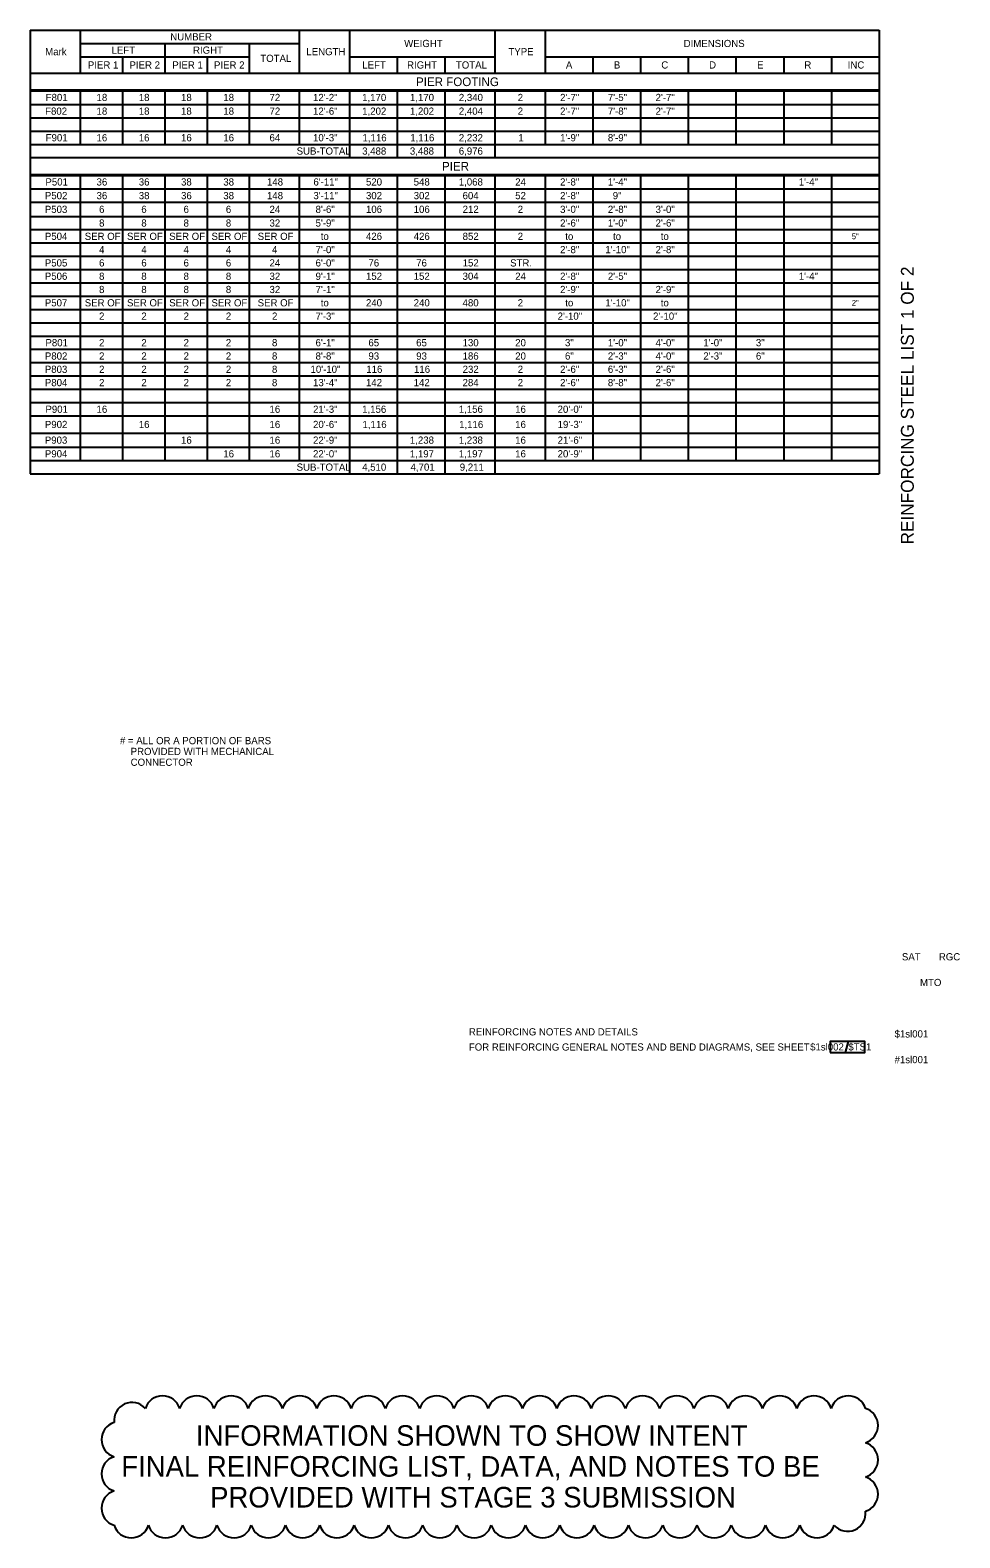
# Model space of a CAD drawing. Extents: x -16.6 to 33.3, y -8.6 to 39.2.
# Drawn here: x 15.24 to 33.32, y -8.63 to 20.7 of the extents above; entities that cross this region are included whole.
import ezdxf

# ---------------------------------------------------------------- set-up
doc = ezdxf.new("R2010")
doc.units = 0
for name, color, linetype in [('BR_X_Beam_Centerline', 7, 'Continuous'), ('BR_X_Beam_Object', 7, 'Continuous'), ('Default', 7, 'Continuous')]:
    doc.layers.add(name, color=color, linetype=linetype)

msp = doc.modelspace()

# ---------------------------------------------------------------- linework, layer by layer
at = {"layer": 'BR_X_Beam_Centerline'}
msp.add_line((31.098, 0.814), (31.153, 1.029), dxfattribs=at)
msp.add_lwpolyline([(30.796, 0.814), (31.47, 0.814), (31.47, 1.029), (30.796, 1.029)], close=True, dxfattribs=at)
for centre, radius, start, end in [((17.221, -6.342), 0.349, 41.6402, 186.6402), ((17.816, -6.215), 0.35, 17.5, 162.5), ((18.482, -6.215), 0.35, 17.5, 162.5), ((19.149, -6.215), 0.35, 17.5, 162.5), ((19.816, -6.215), 0.35, 17.5, 162.5), ((20.483, -6.215), 0.35, 17.5, 162.5), ((21.149, -6.215), 0.35, 17.5, 162.5), ((21.816, -6.215), 0.35, 17.5, 162.5), ((22.483, -6.215), 0.35, 17.5, 162.5), ((23.15, -6.215), 0.35, 17.5, 162.5), ((23.816, -6.215), 0.35, 17.5, 162.5), ((24.483, -6.215), 0.35, 17.5, 162.5), ((25.15, -6.215), 0.35, 17.5, 162.5), ((25.817, -6.215), 0.35, 17.5, 162.5), ((26.483, -6.215), 0.35, 17.5, 162.5), ((27.15, -6.215), 0.35, 17.5, 162.5), ((27.817, -6.215), 0.35, 17.5, 162.5), ((28.484, -6.215), 0.35, 17.5, 162.5), ((29.15, -6.215), 0.35, 17.5, 162.5), ((29.817, -6.215), 0.35, 17.5, 162.5), ((30.484, -6.215), 0.35, 17.5, 162.5), ((31.151, -6.215), 0.35, 17.5, 162.5), ((31.379, -6.443), 0.35, 287.5, 72.5), ((16.979, -6.716), 0.35, 107.5, 252.5), ((31.379, -7.11), 0.35, 287.5, 72.5), ((16.979, -7.382), 0.35, 107.5, 252.5), ((31.379, -7.777), 0.35, 287.5, 72.5), ((16.979, -8.049), 0.35, 107.5, 252.5), ((31.137, -8.151), 0.349, 221.6402, 6.6402), ((17.208, -8.277), 0.35, 197.5, 342.5), ((17.874, -8.277), 0.35, 197.5, 342.5), ((18.541, -8.277), 0.35, 197.5, 342.5), ((19.208, -8.277), 0.35, 197.5, 342.5), ((19.875, -8.277), 0.35, 197.5, 342.5), ((20.541, -8.277), 0.35, 197.5, 342.5), ((21.208, -8.277), 0.35, 197.5, 342.5), ((21.875, -8.277), 0.35, 197.5, 342.5), ((22.542, -8.277), 0.35, 197.5, 342.5), ((23.208, -8.277), 0.35, 197.5, 342.5), ((23.875, -8.277), 0.35, 197.5, 342.5), ((24.542, -8.277), 0.35, 197.5, 342.5), ((25.209, -8.277), 0.35, 197.5, 342.5), ((25.875, -8.277), 0.35, 197.5, 342.5), ((26.542, -8.277), 0.35, 197.5, 342.5), ((27.209, -8.277), 0.35, 197.5, 342.5), ((27.876, -8.277), 0.35, 197.5, 342.5), ((28.542, -8.277), 0.35, 197.5, 342.5), ((29.209, -8.277), 0.35, 197.5, 342.5), ((29.876, -8.277), 0.35, 197.5, 342.5), ((30.543, -8.277), 0.35, 197.5, 342.5)]:
    msp.add_arc(centre, radius, start, end, dxfattribs=at)
at = {"layer": 'Default'}
for p, q in [((15.242, 20.698), (31.752, 20.698)), ((15.242, 20.698), (15.242, 19.516)), ((16.216, 20.698), (16.216, 19.861)), ((20.476, 20.698), (20.476, 19.861)), ((21.45, 20.698), (21.45, 19.861)), ((24.281, 20.698), (24.281, 19.861)), ((25.254, 20.698), (25.254, 19.861)), ((31.752, 20.698), (31.752, 19.516)), ((16.216, 20.439), (20.476, 20.439)), ((17.859, 20.439), (17.859, 19.861)), ((19.503, 20.439), (19.503, 19.861)), ((16.216, 20.181), (19.503, 20.181)), ((17.037, 20.181), (17.037, 19.861)), ((18.681, 20.181), (18.681, 19.861)), ((21.45, 20.181), (24.281, 20.181)), ((22.378, 20.181), (22.378, 19.861)), ((23.307, 20.181), (23.307, 19.861)), ((25.254, 20.181), (31.752, 20.181)), ((26.183, 20.181), (26.183, 19.861)), ((27.111, 20.181), (27.111, 19.861)), ((28.039, 20.181), (28.039, 19.861)), ((28.967, 20.181), (28.967, 19.861)), ((29.896, 20.181), (29.896, 19.861)), ((30.824, 20.181), (30.824, 19.861)), ((15.242, 19.861), (31.752, 19.861)), ((15.242, 19.536), (31.752, 19.536)), ((15.242, 19.536), (15.242, 17.873)), ((15.242, 19.516), (31.752, 19.516)), ((16.216, 19.516), (16.216, 18.476)), ((17.037, 19.516), (17.037, 18.476)), ((17.859, 19.516), (17.859, 18.476)), ((18.681, 19.516), (18.681, 18.476)), ((19.503, 19.536), (19.503, 18.476)), ((20.476, 19.516), (20.476, 18.476)), ((21.45, 19.516), (21.45, 18.218)), ((22.378, 19.516), (22.378, 18.218)), ((23.307, 19.536), (23.307, 18.218)), ((24.281, 19.516), (24.281, 18.218)), ((25.254, 19.516), (25.254, 18.476)), ((26.183, 19.516), (26.183, 18.476)), ((27.111, 19.516), (27.111, 18.476)), ((28.039, 19.516), (28.039, 18.476)), ((28.967, 19.516), (28.967, 18.476)), ((29.896, 19.516), (29.896, 18.476)), ((30.824, 19.516), (30.824, 18.476)), ((31.752, 19.536), (31.752, 17.873)), ((15.242, 19.252), (31.752, 19.252)), ((15.242, 18.994), (31.752, 18.994)), ((15.242, 18.735), (31.752, 18.735)), ((15.242, 18.476), (31.752, 18.476)), ((15.242, 18.218), (31.752, 18.218)), ((15.242, 17.893), (31.752, 17.893)), ((15.242, 17.893), (15.242, 12.07)), ((19.503, 17.893), (19.503, 12.329)), ((23.307, 17.893), (23.307, 12.07)), ((31.752, 17.893), (31.752, 12.07)), ((15.242, 17.873), (31.752, 17.873)), ((15.242, 17.609), (31.752, 17.609)), ((16.216, 17.873), (16.216, 12.329)), ((17.037, 17.873), (17.037, 12.329)), ((17.859, 17.873), (17.859, 12.329)), ((18.681, 17.873), (18.681, 12.329)), ((20.476, 17.873), (20.476, 12.329)), ((21.45, 17.873), (21.45, 12.07)), ((22.378, 17.873), (22.378, 12.07)), ((24.281, 17.873), (24.281, 12.07)), ((25.254, 17.873), (25.254, 12.329)), ((26.183, 17.873), (26.183, 12.329)), ((27.111, 17.873), (27.111, 12.329)), ((28.039, 17.873), (28.039, 12.329)), ((28.967, 17.873), (28.967, 12.329)), ((29.896, 17.873), (29.896, 12.329)), ((30.824, 17.873), (30.824, 12.329)), ((15.242, 17.35), (31.752, 17.35)), ((15.242, 17.076), (31.752, 17.076)), ((15.242, 16.818), (31.752, 16.818)), ((15.242, 16.559), (31.752, 16.559)), ((15.242, 16.3), (31.752, 16.3)), ((15.242, 16.042), (31.752, 16.042)), ((15.242, 15.783), (31.752, 15.783)), ((15.242, 15.524), (31.752, 15.524)), ((15.242, 15.266), (31.752, 15.266)), ((15.242, 15.007), (31.752, 15.007)), ((15.242, 14.748), (31.752, 14.748)), ((15.242, 14.49), (31.752, 14.49)), ((15.242, 14.231), (31.752, 14.231)), ((15.242, 13.972), (31.752, 13.972)), ((15.242, 13.713), (31.752, 13.713)), ((15.242, 13.455), (31.752, 13.455)), ((15.242, 13.196), (31.752, 13.196)), ((15.242, 12.861), (31.752, 12.861)), ((15.242, 12.587), (31.752, 12.587)), ((15.242, 12.329), (31.752, 12.329)), ((15.242, 12.07), (31.753, 12.07))]:
    msp.add_line(p, q, dxfattribs=at)

# ---------------------------------------------------------------- texts
at = {"layer": 'BR_X_Beam_Centerline'}
for s, height, p in [('NUMBER', 0.14, (17.966, 20.499)), ('Mark', 0.14, (15.534, 20.21)), ('LEFT', 0.14, (16.824, 20.24)), ('RIGHT', 0.14, (18.409, 20.24)), ('LENGTH', 0.14, (20.613, 20.21)), ('WEIGHT', 0.14, (22.515, 20.369)), ('TYPE', 0.14, (24.542, 20.21)), ('DIMENSIONS', 0.14, (27.95, 20.369)), ('PIER 1', 0.14, (16.364, 19.951)), ('PIER 2', 0.14, (17.174, 19.951)), ('PIER 1', 0.14, (18.007, 19.951)), ('PIER 2', 0.14, (18.817, 19.951)), ('TOTAL', 0.14, (19.717, 20.08)), ('LEFT', 0.14, (21.701, 19.951)), ('RIGHT', 0.14, (22.571, 19.951)), ('TOTAL', 0.14, (23.521, 19.951)), ('A', 0.14, (25.66, 19.951)), ('B', 0.14, (26.593, 19.951)), ('C', 0.14, (27.515, 19.951)), ('D', 0.14, (28.444, 19.951)), ('E', 0.14, (29.377, 19.951)), ('R', 0.14, (30.297, 19.951)), ('INC', 0.14, (31.14, 19.951)), ('PIER FOOTING', 0.16799, (22.746, 19.61)), ('F801', 0.14, (15.544, 19.319)), ('18', 0.14, (16.533, 19.319)), ('18', 0.14, (17.354, 19.319)), ('18', 0.14, (18.176, 19.319)), ('18', 0.14, (18.998, 19.319)), ('72', 0.14, (19.896, 19.319)), ('12\'-2"', 0.14, (20.743, 19.319)), ('1,170', 0.14, (21.698, 19.319)), ('1,170', 0.14, (22.627, 19.319)), ('2,340', 0.14, (23.578, 19.319)), ('2', 0.14, (24.723, 19.319)), ('2\'-7"', 0.14, (25.547, 19.319)), ('7\'-5"', 0.14, (26.476, 19.319)), ('2\'-7"', 0.14, (27.404, 19.319)), ('F802', 0.14, (15.533, 19.053)), ('18', 0.14, (16.533, 19.053)), ('18', 0.14, (17.354, 19.053)), ('18', 0.14, (18.176, 19.053)), ('18', 0.14, (18.998, 19.053)), ('72', 0.14, (19.896, 19.053)), ('12\'-6"', 0.14, (20.743, 19.053)), ('1,202', 0.14, (21.699, 19.053)), ('1,202', 0.14, (22.627, 19.053)), ('2,404', 0.14, (23.578, 19.053)), ('2', 0.14, (24.723, 19.053)), ('2\'-7"', 0.14, (25.547, 19.053)), ('7\'-8"', 0.14, (26.476, 19.053)), ('2\'-7"', 0.14, (27.404, 19.053)), ('F901', 0.14, (15.544, 18.536)), ('16', 0.14, (16.533, 18.536)), ('16', 0.14, (17.354, 18.536)), ('16', 0.14, (18.176, 18.536)), ('16', 0.14, (18.998, 18.536)), ('64', 0.14, (19.896, 18.536)), ('10\'-3"', 0.14, (20.743, 18.536)), ('1,116', 0.14, (21.705, 18.536)), ('1,116', 0.14, (22.633, 18.536)), ('2,232', 0.14, (23.578, 18.536)), ('1', 0.14, (24.735, 18.536)), ('1\'-9"', 0.14, (25.547, 18.536)), ('8\'-9"', 0.14, (26.476, 18.536)), ('SUB-TOTAL', 0.14, (20.424, 18.277)), ('3,488', 0.14, (21.698, 18.277)), ('3,488', 0.14, (22.626, 18.277)), ('6,976', 0.14, (23.577, 18.277)), ('PIER', 0.168, (23.251, 17.966)), ('P501', 0.14, (15.539, 17.676)), ('36', 0.14, (16.533, 17.676)), ('36', 0.14, (17.354, 17.676)), ('38', 0.14, (18.176, 17.676)), ('38', 0.14, (18.998, 17.676)), ('148', 0.14, (19.847, 17.676)), ('6\'-11"', 0.14, (20.75, 17.676)), ('520', 0.14, (21.772, 17.676)), ('548', 0.14, (22.7, 17.676)), ('1,068', 0.14, (23.577, 17.676)), ('24', 0.14, (24.674, 17.676)), ('2\'-8"', 0.14, (25.547, 17.676)), ('1\'-4"', 0.14, (26.476, 17.676)), ('1\'-4"', 0.14, (30.189, 17.676)), ('P502', 0.14, (15.528, 17.41)), ('36', 0.14, (16.533, 17.41)), ('38', 0.14, (17.354, 17.41)), ('36', 0.14, (18.176, 17.41)), ('38', 0.14, (18.998, 17.41)), ('148', 0.14, (19.847, 17.41)), ('3\'-11"', 0.14, (20.75, 17.41)), ('302', 0.14, (21.772, 17.41)), ('302', 0.14, (22.7, 17.41)), ('604', 0.14, (23.651, 17.41)), ('52', 0.14, (24.674, 17.41)), ('2\'-8"', 0.14, (25.547, 17.41)), ('9"', 0.14, (26.571, 17.41)), ('P503', 0.14, (15.527, 17.143)), ('8', 0.14, (16.582, 16.877)), ('6', 0.14, (16.582, 17.143)), ('8', 0.14, (17.403, 16.877)), ('6', 0.14, (17.403, 17.143)), ('8', 0.14, (18.225, 16.877)), ('6', 0.14, (18.225, 17.143)), ('8', 0.14, (19.047, 16.877)), ('6', 0.14, (19.047, 17.143)), ('32', 0.14, (19.896, 16.877)), ('24', 0.14, (19.896, 17.143)), ('8\'-6"', 0.14, (20.792, 17.143)), ('5\'-9"', 0.14, (20.792, 16.877)), ('106', 0.14, (21.772, 17.143)), ('106', 0.14, (22.7, 17.143)), ('212', 0.14, (23.652, 17.143)), ('2', 0.14, (24.723, 17.143)), ('3\'-0"', 0.14, (25.547, 17.143)), ('2\'-6"', 0.14, (25.547, 16.877)), ('2\'-8"', 0.14, (26.476, 17.143)), ('1\'-0"', 0.14, (26.476, 16.877)), ('3\'-0"', 0.14, (27.404, 17.143)), ('2\'-6"', 0.14, (27.404, 16.877)), ('P504', 0.14, (15.528, 16.618)), ('SER OF', 0.14, (16.303, 16.618)), ('SER OF', 0.14, (17.125, 16.618)), ('SER OF', 0.14, (17.946, 16.618)), ('SER OF', 0.14, (18.768, 16.618)), ('SER OF', 0.14, (19.666, 16.618)), ('to', 0.14, (20.893, 16.618)), ('426', 0.14, (21.772, 16.618)), ('426', 0.14, (22.7, 16.618)), ('852', 0.14, (23.652, 16.618)), ('2', 0.14, (24.723, 16.618)), ('to', 0.14, (25.648, 16.618)), ('to', 0.14, (26.577, 16.618)), ('to', 0.14, (27.505, 16.618)), ('5"', 0.112, (31.219, 16.632)), ('4', 0.14, (16.582, 16.36)), ('4', 0.14, (17.404, 16.36)), ('4', 0.14, (18.225, 16.36)), ('4', 0.14, (19.047, 16.36)), ('4', 0.14, (19.945, 16.36)), ('7\'-0"', 0.14, (20.792, 16.36)), ('2\'-8"', 0.14, (25.547, 16.36)), ('1\'-10"', 0.14, (26.427, 16.36)), ('2\'-8"', 0.14, (27.404, 16.36)), ('P505', 0.14, (15.527, 16.101)), ('6', 0.14, (16.582, 16.101)), ('6', 0.14, (17.403, 16.101)), ('6', 0.14, (18.225, 16.101)), ('6', 0.14, (19.047, 16.101)), ('24', 0.14, (19.896, 16.101)), ('6\'-0"', 0.14, (20.792, 16.101)), ('76', 0.14, (21.82, 16.101)), ('76', 0.14, (22.749, 16.101)), ('152', 0.14, (23.652, 16.101)), ('STR.', 0.14, (24.575, 16.101)), ('P506', 0.14, (15.527, 15.842)), ('8', 0.14, (16.582, 15.842)), ('8', 0.14, (17.403, 15.842)), ('8', 0.14, (18.225, 15.842)), ('8', 0.14, (19.047, 15.842)), ('32', 0.14, (19.896, 15.842)), ('9\'-1"', 0.14, (20.792, 15.842)), ('152', 0.14, (21.772, 15.842)), ('152', 0.14, (22.7, 15.842)), ('304', 0.14, (23.651, 15.842)), ('24', 0.14, (24.674, 15.842)), ('2\'-8"', 0.14, (25.547, 15.842)), ('2\'-5"', 0.14, (26.476, 15.842)), ('1\'-4"', 0.14, (30.189, 15.842)), ('8', 0.14, (16.582, 15.584)), ('8', 0.14, (17.403, 15.584)), ('8', 0.14, (18.225, 15.584)), ('8', 0.14, (19.047, 15.584)), ('32', 0.14, (19.896, 15.584)), ('7\'-1"', 0.14, (20.792, 15.584)), ('2\'-9"', 0.14, (25.547, 15.584)), ('2\'-9"', 0.14, (27.404, 15.584)), ('P507', 0.14, (15.527, 15.325)), ('SER OF', 0.14, (16.303, 15.325)), ('SER OF', 0.14, (17.125, 15.325)), ('SER OF', 0.14, (17.946, 15.325)), ('SER OF', 0.14, (18.768, 15.325)), ('SER OF', 0.14, (19.666, 15.325)), ('to', 0.14, (20.893, 15.325)), ('240', 0.14, (21.772, 15.325)), ('240', 0.14, (22.7, 15.325)), ('480', 0.14, (23.651, 15.325)), ('2', 0.14, (24.723, 15.325)), ('to', 0.14, (25.648, 15.325)), ('1\'-10"', 0.14, (26.427, 15.325)), ('to', 0.14, (27.505, 15.325)), ('2"', 0.112, (31.219, 15.339)), ('2', 0.14, (16.582, 15.066)), ('2', 0.14, (17.404, 15.066)), ('2', 0.14, (18.226, 15.066)), ('2', 0.14, (19.047, 15.066)), ('2', 0.14, (19.945, 15.066)), ('7\'-3"', 0.14, (20.792, 15.066)), ('2\'-10"', 0.14, (25.499, 15.066)), ('2\'-10"', 0.14, (27.355, 15.066)), ('P801', 0.14, (15.539, 14.549)), ('2', 0.14, (16.582, 14.549)), ('2', 0.14, (17.404, 14.549)), ('2', 0.14, (18.226, 14.549)), ('2', 0.14, (19.047, 14.549)), ('8', 0.14, (19.944, 14.549)), ('6\'-1"', 0.14, (20.792, 14.549)), ('65', 0.14, (21.82, 14.549)), ('65', 0.14, (22.748, 14.549)), ('130', 0.14, (23.651, 14.549)), ('20', 0.14, (24.674, 14.549)), ('3"', 0.14, (25.642, 14.549)), ('1\'-0"', 0.14, (26.476, 14.549)), ('4\'-0"', 0.14, (27.404, 14.549)), ('1\'-0"', 0.14, (28.332, 14.549)), ('3"', 0.14, (29.355, 14.549)), ('P802', 0.14, (15.528, 14.29)), ('2', 0.14, (16.582, 14.29)), ('2', 0.14, (17.404, 14.29)), ('2', 0.14, (18.226, 14.29)), ('2', 0.14, (19.047, 14.29)), ('8', 0.14, (19.944, 14.29)), ('8\'-8"', 0.14, (20.792, 14.29)), ('93', 0.14, (21.82, 14.29)), ('93', 0.14, (22.749, 14.29)), ('186', 0.14, (23.651, 14.29)), ('20', 0.14, (24.674, 14.29)), ('6"', 0.14, (25.642, 14.29)), ('2\'-3"', 0.14, (26.476, 14.29)), ('4\'-0"', 0.14, (27.404, 14.29)), ('2\'-3"', 0.14, (28.332, 14.29)), ('6"', 0.14, (29.355, 14.29)), ('P803', 0.14, (15.527, 14.032)), ('2', 0.14, (16.582, 14.032)), ('2', 0.14, (17.404, 14.032)), ('2', 0.14, (18.226, 14.032)), ('2', 0.14, (19.047, 14.032)), ('8', 0.14, (19.944, 14.032)), ('10\'-10"', 0.14, (20.694, 14.032)), ('116', 0.14, (21.778, 14.032)), ('116', 0.14, (22.706, 14.032)), ('232', 0.14, (23.652, 14.032)), ('2', 0.14, (24.723, 14.032)), ('2\'-6"', 0.14, (25.547, 14.032)), ('6\'-3"', 0.14, (26.476, 14.032)), ('2\'-6"', 0.14, (27.404, 14.032)), ('P804', 0.14, (15.528, 13.773)), ('2', 0.14, (16.582, 13.773)), ('2', 0.14, (17.404, 13.773)), ('2', 0.14, (18.226, 13.773)), ('2', 0.14, (19.047, 13.773)), ('8', 0.14, (19.944, 13.773)), ('13\'-4"', 0.14, (20.743, 13.773)), ('142', 0.14, (21.772, 13.773)), ('142', 0.14, (22.7, 13.773)), ('284', 0.14, (23.651, 13.773)), ('2', 0.14, (24.723, 13.773)), ('2\'-6"', 0.14, (25.547, 13.773)), ('8\'-8"', 0.14, (26.476, 13.773)), ('2\'-6"', 0.14, (27.404, 13.773)), ('P901', 0.14, (15.539, 13.255)), ('16', 0.14, (16.533, 13.255)), ('16', 0.14, (19.896, 13.255)), ('21\'-3"', 0.14, (20.743, 13.255)), ('1,156', 0.14, (21.698, 13.255)), ('1,156', 0.14, (23.577, 13.255)), ('16', 0.14, (24.674, 13.255)), ('20\'-0"', 0.14, (25.499, 13.255)), ('P902', 0.14, (15.528, 12.959)), ('16', 0.14, (17.354, 12.959)), ('16', 0.14, (19.896, 12.959)), ('20\'-6"', 0.14, (20.743, 12.959)), ('1,116', 0.14, (21.705, 12.959)), ('1,116', 0.14, (23.584, 12.959)), ('16', 0.14, (24.674, 12.959)), ('19\'-3"', 0.14, (25.499, 12.959)), ('P903', 0.14, (15.527, 12.654)), ('16', 0.14, (18.176, 12.654)), ('16', 0.14, (19.896, 12.654)), ('22\'-9"', 0.14, (20.743, 12.654)), ('1,238', 0.14, (22.626, 12.654)), ('1,238', 0.14, (23.577, 12.654)), ('16', 0.14, (24.674, 12.654)), ('21\'-6"', 0.14, (25.499, 12.654)), ('P904', 0.14, (15.528, 12.388)), ('16', 0.14, (18.998, 12.388)), ('16', 0.14, (19.896, 12.388)), ('22\'-0"', 0.14, (20.743, 12.388)), ('1,197', 0.14, (22.626, 12.388)), ('1,197', 0.14, (23.577, 12.388)), ('16', 0.14, (24.674, 12.388)), ('20\'-9"', 0.14, (25.499, 12.388)), ('SUB-TOTAL', 0.14, (20.424, 12.129)), ('4,510', 0.14, (21.698, 12.129)), ('4,701', 0.14, (22.639, 12.129)), ('9,211', 0.14, (23.596, 12.129)), ('# = ALL OR A PORTION OF BARS ', 0.14, (16.988, 6.809)), ('    CONNECTOR', 0.14, (16.988, 6.389)), ('    PROVIDED WITH MECHANICAL ', 0.14, (16.988, 6.599)), ('REINFORCING NOTES AND DETAILS', 0.14, (23.773, 1.145)), ('FOR REINFORCING GENERAL NOTES AND BEND DIAGRAMS, SEE SHEET', 0.14, (23.773, 0.85)), ('$1sl002', 0.14, (30.409, 0.852)), ('$TS1', 0.14, (31.152, 0.852)), ('INFORMATION SHOWN TO SHOW INTENT', 0.4, (18.465, -6.837)), ('FINAL REINFORCING LIST, DATA, AND NOTES TO BE ', 0.4, (17.014, -7.437)), ('PROVIDED WITH STAGE 3 SUBMISSION', 0.4, (18.742, -8.037))]:
    msp.add_text(s, height=height, dxfattribs=at).set_placement(p)
msp.add_text('REINFORCING STEEL LIST 1 OF 2', height=0.25, rotation=90, dxfattribs=at).set_placement((32.425, 10.695))
at = {"layer": 'BR_X_Beam_Object'}
for s, p in [('SAT', (32.194, 2.605)), ('RGC', (32.912, 2.605)), ('MTO', (32.546, 2.105)), ('$1sl001', (32.051, 1.105)), ('#1sl001', (32.051, 0.605))]:
    msp.add_text(s, height=0.14, dxfattribs=at).set_placement(p)

doc.saveas('drawing.dxf')
